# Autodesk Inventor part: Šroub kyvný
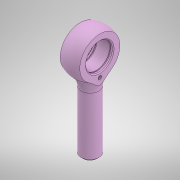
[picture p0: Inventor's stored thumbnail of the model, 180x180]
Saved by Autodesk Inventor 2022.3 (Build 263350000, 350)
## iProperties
Created: 2024-12
Part Number: Šroub kyvný
Material: Všeobecné
Document SubType Name: Modeling
Designer: Hra42
Density: 1 g/cm^3
Appearance: Výchozí
Author: Hra42
Sending System: SolidWorks 2012
Last Author: Hra42
Last Saved: 2025-11-10
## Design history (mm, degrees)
node "Šroub kyvný.SLDPRT"
node "Těleso1"
feature "T_X2_011B_X0_leso1"
